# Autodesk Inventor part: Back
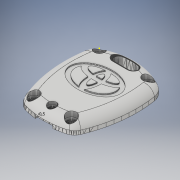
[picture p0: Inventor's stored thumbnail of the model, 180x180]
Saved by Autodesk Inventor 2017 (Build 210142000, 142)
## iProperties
Created: 2017-03
Part Number: Back
Material: Generic
Document SubType Name: Modeling
Designer: turin
Density: 1 g/cm^3
Appearance: Default
Author: turin
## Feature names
1. Sweep1
2. Extrusion1
3. Extrusion2
4. Base1
## Parameters: d0 = 15 mm, d1 = 0, d2 = 0, d5 = 0, d8 = 0.6 mm, d9 = 0, d10 = 0.5 mm
